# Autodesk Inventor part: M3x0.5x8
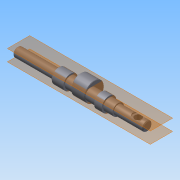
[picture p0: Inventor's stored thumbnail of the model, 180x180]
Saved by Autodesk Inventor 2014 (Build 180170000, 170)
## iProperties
Company: 한국ATC센터
Created: 2009-02
Part Number: M3x0.5x8
Document SubType Name: Modeling
Designer: KYOUNG IL JANG
Density: 7.86 g/cm^3
Mass: 246.092 g
Surface Area: 95.1288 cm^2
Volume: 31.3094 cm^3
Material: 강, 연강
Vendor: CBT Solutions
Appearance: 강철
Author: KYOUNG IL JANG
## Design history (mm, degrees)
sketch "스케치1"
  geometry: L1 (-84.5, 0)-(84.5, 0); L2 (-84.5, 0)-(-84.5, 6); L3 (-84.5, 6)-(-30.5, 6); L4 (-30.5, 6)-(-30.5, 9.5); L5 (-30.5, 9.5)-(-15.5, 9.5); L6 (-15.5, 9.5)-(-15.5, 7.5); L7 (-15.5, 7.5)-(46.5, 7.5); L8 (84.5, 6)-(84.5, 0); L9 (34.5, 7.5)-(34.5, 9.5); L10 (34.5, 9.5)-(24.5, 9.5); L11 (24.5, 9.5)-(24.5, 7.5); L12 (46.5, 7.5)-(46.5, 6); L13 (46.5, 6)-(84.5, 6); 2 further points
  constraints: 26 end point, 6 parallel, 6 perpendicular, 2 point on line, 1 coincident, 1 horizontal, 1 midpoint
  dimensions: "d1" = 12 diameter of L3 L1; "d2" = 15 diameter of L7 L1; "d4" = 15 distance of L4.end L5.end; "d5" = 19 diameter of L5 L1; "d24" = 10 distance of L9.end L10.end; "d25" = 19 diameter of L10 L1; "d27" = 40 distance between parallel lines of L11 L6; "d28" = 54 distance of L2.end L3.end; "d29" = 50 distance between parallel lines of L8 L9; "d41" = 38 distance between parallel lines of L8 L12; "d42" = 12 diameter of L13 L1
revolve "회전1" stored, may be unused: angle "d6" = 90 deg
node "작업 평면1"
sketch "스케치2"
  geometry: C1 r 7.5 at (0, 0) reference; C2 r 12.5 at (0, 4.5); 1 further point
  constraints: 1 centre point, 1 vertical alignment
  dimensions: "d8" = 4.5 distance of point (0, 0) C2.centre; "d9" = 25 diameter of C2
extrude "돌출1" join sketch "스케치2" distance "d10" = 18; taper "d11" = 0 deg
chamfer "모따기1" distance "d12" = 1; stored, may be unused: second distance "d13" = 2, angle "d14" = 45 deg
chamfer "모따기2" distance "d15" = 0.5; stored, may be unused: second distance "d16" = 2, angle "d17" = 45 deg
node "작업 평면2"
sketch "스케치3"
  geometry: L1 (4, -2)-(18, -2); L2 (18, 2)-(4, 2); L3 (27, 5)-(27, -5) reference; A1 r 2 centre (18, 0) between (18, -2) and (18, 2); A2 r 2 centre (4, 0) between (4, 2) and (4, -2); 2 further points
  constraints: 4 end point, 4 point on circle, 4 tangent, 2 centre point, 1 horizontal, 1 horizontal alignment, 1 midpoint, 1 parallel
  dimensions: "d18" = 7 distance edge to line of A1 L3; "d19" = 4 distance between parallel lines of L2 L1; "d20" = 18 dimension on A1 A2
extrude "돌출2" cut sketch "스케치3" distance "d21" = 2.5; taper "d22" = 0 deg
revolve "회전2" stored, may be unused: angle "d26" = 90 deg
node "작업 평면3"
sketch "스케치4"
  geometry: L1 (44, 5)-(44, -5) reference; 2 further points
  constraints: 1 horizontal alignment
  dimensions: "d30" = 12 distance from line of point (32, 0) L1
hole "구멍1" sketch "스케치4" at (32, 0) diameter "d31" = 9; stored, may be unused: countersink angle "d35" = 90 deg, drill point angle "d37" = 118 deg; dims "d32" = 6, "d33" = 14, "d34" = 3, "d36" = 8
node "작업 평면4"
sketch "스케치5"
  geometry: C1 r 8 at (32, 0); A1 r 4.5 centre (32, 0) between (29.879, 3.969) and (29.879, -3.969) reference; A2 r 4.5 centre (32, 0) between (34.121, -3.969) and (34.121, 3.969) reference; 1 further point
  constraints: 2 horizontal alignment, 1 centre point, 1 coincident
  dimensions: "d38" = 16 diameter of C1
extrude "돌출3" cut sketch "스케치5" distance "d39" = 3; taper "d40" = 0 deg
node "솔리드1"
node "투영된 루프1"
other parameters: "d7" = 8.5
